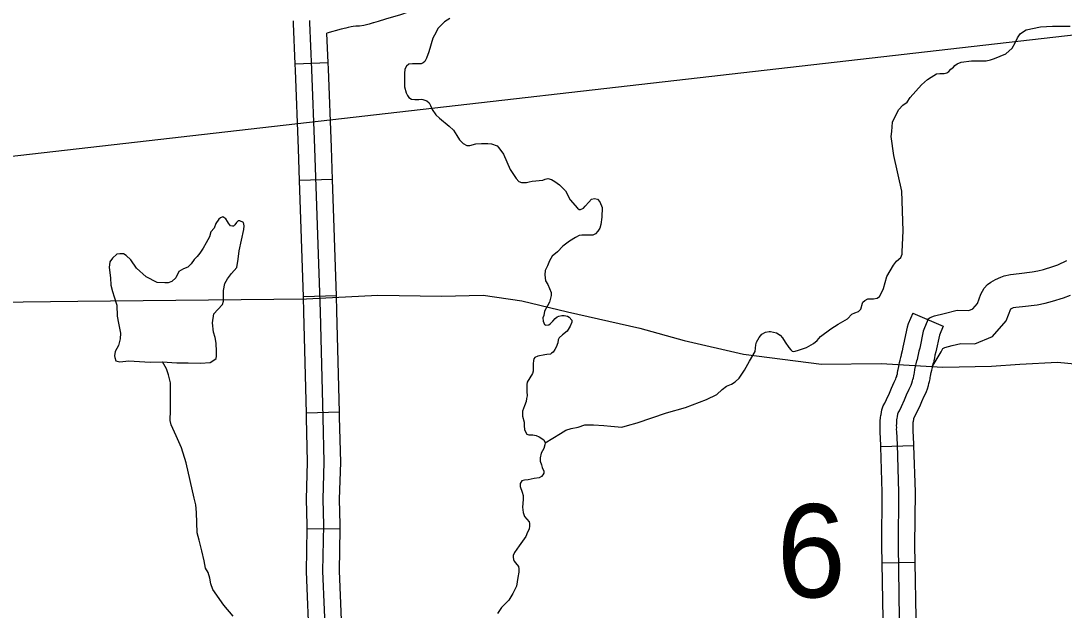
# Model space of a CAD drawing. Extents: x 1720274 to 1751788, y 372074 to 391887.
# Drawn here: x 1730713 to 1731462, y 376592 to 377014 of the extents above; entities that cross this region are included whole.
import ezdxf

# ---------------------------------------------------------------- set-up
doc = ezdxf.new("R2010")
doc.units = 0
for name, color, linetype in [('Level 32', 7, 'Continuous'), ('Level 35', 7, 'Continuous'), ('Level 43', 7, 'Continuous'), ('Level 46', 7, 'Continuous'), ('Level 5', 7, 'Continuous'), ('R_Draft', 7, 'Continuous')]:
    doc.layers.add(name, color=color, linetype=linetype)

msp = doc.modelspace()

# ---------------------------------------------------------------- linework, layer by layer
at = {"layer": 'Level 32'}
for p, q in [((1730933.83, 376984.27), (1730910.15, 376983.28)), ((1730936.9, 376900.8), (1730913.21, 376900.01)), ((1730939.71, 376817.43), (1730916.02, 376816.63)), ((1731352.96, 376804.81), (1731374.78, 376795.56)), ((1730941.88, 376733.93), (1730918.18, 376733.34)), ((1731353.87, 376709.77), (1731330.18, 376709.05)), ((1730942.4, 376650.07), (1730918.71, 376650.41)), ((1731354.76, 376626.18), (1731331.07, 376625.82))]:
    msp.add_line(p, q, dxfattribs=at)
for points in [[(1731042.66, 377038.36), (1731042.39, 377038.35), (1731040.21, 377037.88), (1731036.36, 377036.96), (1731032.32, 377036.02), (1731027.97, 377034.93), (1731022.21, 377033.15), (1731018.32, 377031.73), (1731016.08, 377030.9), (1731013.33, 377029.8), (1731008.24, 377027.48), (1730995.23, 377022.12), (1730985.7, 377018.8), (1730974.95, 377015.65), (1730969.76, 377014), (1730966.42, 377013.01)], [(1730910.15, 376983.28), (1730908.93, 377012.6), (1730908.88, 377014.4)], [(1730932.45, 376564.63), (1730930.11, 376619.99), (1730930.6, 376653.04), (1730930.12, 376671.6), (1730930.97, 376698.04), (1730930.12, 376730.24), (1730928.24, 376805.99), (1730924.28, 376923.2), (1730922.17, 376979.44), (1730920.77, 377013), (1730920.73, 377014.7)], [(1730966.42, 377013.01), (1730966.04, 377012.9), (1730964.77, 377012.57), (1730963.13, 377012.02), (1730959.48, 377011.15), (1730956.31, 377010.67), (1730953.62, 377010.53), (1730951.73, 377010.31), (1730950.32, 377010.02), (1730948.17, 377009.62), (1730946.46, 377009.2), (1730943.14, 377008.34), (1730932.94, 377005.66)], [(1730933.83, 376984.27), (1730932.94, 377005.66)], [(1730913.21, 376900.01), (1730912.44, 376922.78), (1730910.33, 376978.97), (1730910.15, 376983.28)], [(1730936.9, 376900.8), (1730936.13, 376923.63), (1730934.01, 376979.91), (1730933.83, 376984.27)], [(1730916.02, 376816.63), (1730913.21, 376900.01)], [(1730939.71, 376817.43), (1730936.9, 376900.8)], [(1730918.18, 376733.34), (1730916.39, 376805.64), (1730916.02, 376816.63)], [(1730941.88, 376733.93), (1730940.08, 376806.33), (1730939.71, 376817.43)], [(1731352.96, 376804.81), (1731349.72, 376797.18), (1731349.06, 376794.92), (1731346.46, 376782.6), (1731345.92, 376780.49), (1731345.33, 376777.96), (1731344.79, 376775.42), (1731344.45, 376773.57)], [(1731363.87, 376800.19), (1731360.9, 376793.18), (1731360.56, 376792.03), (1731358, 376779.89), (1731357.42, 376777.65), (1731356.9, 376775.39), (1731356.42, 376773.13), (1731356.1, 376771.41)], [(1731374.78, 376795.56), (1731372.07, 376789.18), (1731372.06, 376789.13), (1731369.54, 376777.19), (1731368.93, 376774.81), (1731368.47, 376772.83), (1731368.05, 376770.83), (1731367.76, 376769.26)], [(1731330.18, 376709.05), (1731330.14, 376710.25), (1731329.65, 376719.73), (1731329.6, 376721.52), (1731329.62, 376722.75), (1731329.54, 376724.39), (1731329.61, 376725.88), (1731329.61, 376727.56), (1731329.88, 376730.05), (1731330.15, 376731.58), (1731330.28, 376732.41), (1731330.8, 376735.7), (1731331.72, 376738.45), (1731332.88, 376740.48), (1731334.13, 376743.08), (1731336.3, 376747.7), (1731337.78, 376751.22), (1731339.77, 376755.46), (1731340.4, 376756.82), (1731340.8, 376757.75), (1731341.2, 376758.77), (1731341.48, 376759.6), (1731341.62, 376760.23), (1731341.94, 376761.39), (1731342.12, 376762.28), (1731342.4, 376763.77), (1731342.57, 376764.48), (1731342.91, 376766.66), (1731343.51, 376769.47), (1731343.97, 376771.3), (1731344.38, 376773.19), (1731344.45, 376773.57)], [(1731343.51, 376586.21), (1731342.73, 376638.38), (1731343.01, 376676.74), (1731341.98, 376710.74), (1731341.49, 376720.21), (1731341.45, 376721.57), (1731341.48, 376722.94), (1731341.4, 376724.4), (1731341.46, 376725.59), (1731341.46, 376726.93), (1731341.62, 376728.38), (1731341.83, 376729.59), (1731341.98, 376730.54), (1731342.35, 376732.89), (1731342.58, 376733.59), (1731343.37, 376734.96), (1731344.83, 376737.99), (1731347.13, 376742.88), (1731348.61, 376746.41), (1731350.51, 376750.45), (1731351.23, 376752), (1731351.77, 376753.26), (1731352.33, 376754.7), (1731352.89, 376756.35), (1731353.12, 376757.35), (1731353.48, 376758.67), (1731353.75, 376760.03), (1731353.98, 376761.26), (1731354.2, 376762.15), (1731354.57, 376764.51), (1731355.06, 376766.79), (1731355.51, 376768.6), (1731356, 376770.85), (1731356.1, 376771.41)], [(1731353.87, 376709.77), (1731353.82, 376711.23), (1731353.33, 376720.69), (1731353.3, 376721.63), (1731353.33, 376723.13), (1731353.27, 376724.42), (1731353.31, 376725.3), (1731353.31, 376726.3), (1731353.35, 376726.72), (1731353.51, 376727.6), (1731353.68, 376728.67), (1731353.78, 376729.3), (1731353.86, 376729.44), (1731355.53, 376732.9), (1731357.96, 376738.06), (1731359.45, 376741.59), (1731361.25, 376745.44), (1731362.05, 376747.18), (1731362.74, 376748.78), (1731363.46, 376750.63), (1731364.31, 376753.1), (1731364.62, 376754.48), (1731365.02, 376755.96), (1731365.38, 376757.77), (1731365.57, 376758.74), (1731365.83, 376759.82), (1731366.23, 376762.36), (1731366.6, 376764.11), (1731367.05, 376765.9), (1731367.62, 376768.51), (1731367.76, 376769.26)], [(1730918.71, 376650.42), (1730918.74, 376652.98), (1730918.26, 376671.63), (1730919.11, 376698.07), (1730918.27, 376729.94), (1730918.18, 376733.34)], [(1730942.4, 376650.07), (1730942.45, 376653.11), (1730941.97, 376671.56), (1730942.82, 376698.01), (1730941.96, 376730.54), (1730941.88, 376733.93)], [(1731331.07, 376625.82), (1731330.88, 376638.33), (1731331.16, 376676.61), (1731330.18, 376709.05)], [(1731354.76, 376626.18), (1731354.58, 376638.42), (1731354.86, 376676.88), (1731353.87, 376709.77)], [(1730920.51, 376566.37), (1730918.26, 376619.82), (1730918.71, 376650.41)], [(1730944.19, 376567.37), (1730941.97, 376620.15), (1730942.4, 376650.07)], [(1731333.51, 376542.16), (1731332.87, 376558.69), (1731331.67, 376585.86), (1731331.07, 376625.82)], [(1731357.19, 376543.08), (1731356.55, 376559.67), (1731355.36, 376586.56), (1731354.76, 376626.18)]]:
    msp.add_lwpolyline(points, dxfattribs=at)
at = {"layer": 'Level 35'}
for points in [[(1731021.01, 377016.14), (1731017.31, 377013.67), (1731014.84, 377011.43), (1731012.38, 377008.85), (1731011.15, 377006.27), (1731008.79, 377002.11), (1731005.99, 376992.13), (1731004.42, 376987.76), (1731003.19, 376985.4), (1731001.96, 376984.28), (1731000.39, 376983.72), (1730998.82, 376983.72), (1730997.25, 376983.72), (1730994.22, 376983.61), (1730991.76, 376983.27), (1730990.08, 376981.92), (1730988.85, 376979.79), (1730988.62, 376976.76), (1730988.62, 376967.23), (1730989.85, 376962.85), (1730990.64, 376960.95), (1730991.76, 376959.38), (1730993.66, 376958.25), (1730995.91, 376958.03), (1730997.25, 376958.14), (1730998.93, 376958.14), (1731000.5, 376958.25), (1731001.62, 376958.14), (1731004.65, 376957.02), (1731006.33, 376955.56), (1731007.11, 376953.77), (1731008.34, 376950.96), (1731010.92, 376947.15), (1731013.72, 376944.57), (1731020.67, 376938.85), (1731023.58, 376936.04), (1731026.05, 376932.23), (1731028.07, 376929.09), (1731030.64, 376926.4), (1731033.33, 376925.05), (1731035.46, 376925.16), (1731039.72, 376926.28), (1731043.76, 376926.62), (1731048.35, 376926.4), (1731051.04, 376926.17), (1731054.96, 376924.82), (1731056.31, 376923.37), (1731059.56, 376918.77), (1731064.38, 376907.77), (1731068.63, 376901.38), (1731070.54, 376899.36), (1731072.33, 376898.58), (1731076.14, 376898.58), (1731077.94, 376899.02), (1731080.06, 376899.59), (1731087.68, 376900.15), (1731089.48, 376900.93), (1731091.38, 376901.38), (1731093.85, 376900.82), (1731096.31, 376899.25), (1731099.79, 376896.89), (1731104.05, 376892.63), (1731107.41, 376886.24), (1731112.56, 376880.07), (1731113.91, 376879.28), (1731114.69, 376879.28), (1731116.93, 376880.18), (1731118.17, 376881.64), (1731120.63, 376884.44), (1731122.54, 376886.57), (1731124.89, 376887.13), (1731126.91, 376886.69), (1731128.7, 376884.78), (1731130.27, 376880.74), (1731130.16, 376873.67), (1731129.26, 376868.4), (1731128.7, 376865.93), (1731127.24, 376863.69), (1731125.45, 376861.78), (1731123.55, 376860.77)], [(1731429.93, 377005.05), (1731431.66, 377006.39), (1731434.35, 377007.93), (1731444.52, 377010.04), (1731453.16, 377010.62), (1731465.83, 377010.62)], [(1731089.48, 376711.92), (1731100.3, 376718.73), (1731104.34, 376721.03), (1731108.17, 376722.38), (1731112.97, 376723.15), (1731117.97, 376724.88), (1731124.11, 376724.88), (1731131.4, 376724.49), (1731136.59, 376723.91), (1731144.46, 376723.15), (1731148.49, 376724.49), (1731155.4, 376726.22), (1731176.33, 376733.52), (1731189.96, 376737.37), (1731205.12, 376743.13), (1731212.42, 376746.59), (1731216.26, 376750.24), (1731219.52, 376752.55), (1731222.98, 376754.08), (1731225.67, 376755.62), (1731228.55, 376758.31), (1731232.39, 376764.08), (1731235.84, 376770.42), (1731240.06, 376777.53), (1731240.45, 376782.14), (1731240.83, 376784.25), (1731242.75, 376787.52), (1731244.86, 376789.83), (1731247.36, 376791.36), (1731250.05, 376791.75), (1731251.01, 376791.75), (1731255.23, 376790.79), (1731257.92, 376789.25), (1731259.65, 376787.14), (1731261.57, 376784.25), (1731264.25, 376780.22), (1731265.6, 376778.68), (1731266.56, 376777.72), (1731267.71, 376777.53), (1731270.4, 376778.1), (1731276.73, 376780.41), (1731281.92, 376783.1), (1731284.41, 376785.41), (1731286.91, 376788.29), (1731294.2, 376793.67), (1731299.39, 376796.94), (1731306.11, 376800.78), (1731309.37, 376804.24), (1731311.48, 376805.2), (1731314.17, 376806.16), (1731315.7, 376807.7), (1731317.05, 376812.12), (1731317.24, 376812.89), (1731318.58, 376814.04), (1731320.7, 376815.19), (1731324.73, 376815.19), (1731327.41, 376815.77), (1731329.14, 376816.92), (1731330.1, 376818.65), (1731332.02, 376822.69), (1731334.33, 376831.14), (1731339.13, 376839.4), (1731341.24, 376842.29), (1731344.5, 376844.78), (1731345.46, 376847.09), (1731345.46, 376848.82), (1731346.04, 376863.81), (1731345.08, 376892.25), (1731339.51, 376917.81), (1731337.4, 376931.45), (1731337.97, 376935.1), (1731338.36, 376941.83), (1731340.66, 376946.25), (1731342.97, 376950.86), (1731345.84, 376953.93), (1731348.92, 376956.24), (1731351.22, 376959.5), (1731359.28, 376968.54), (1731363.51, 376972.38), (1731366.19, 376974.11), (1731370.03, 376976.42), (1731372.34, 376976.61), (1731374.07, 376976.8), (1731375.41, 376976.8), (1731377.52, 376977.18), (1731378.87, 376978.14), (1731380.21, 376979.68), (1731382.13, 376981.22), (1731383.28, 376982.37), (1731384.82, 376983.72), (1731387.7, 376984.87), (1731395.18, 376985.83), (1731399.98, 376985.83), (1731405.74, 376985.83), (1731408.62, 376986.41), (1731411.69, 376987.37), (1731419.76, 376990.83), (1731424.17, 376994.86), (1731426.48, 376998.71), (1731428.01, 377002.36), (1731429.93, 377005.05)], [(1731123.55, 376860.77), (1731120.52, 376860.77), (1731118.39, 376860.77), (1731115.81, 376860.88), (1731113.91, 376860.66), (1731111.11, 376859.2), (1731106.85, 376856.51), (1731102.14, 376852.92), (1731098.33, 376848.88), (1731094.52, 376845.85), (1731092.5, 376842.49), (1731091.05, 376838.79), (1731089.48, 376835.42), (1731089.14, 376832.39), (1731089.7, 376828.13), (1731091.38, 376825.55), (1731093.74, 376819.83), (1731093.74, 376817.7), (1731092.5, 376812.76), (1731091.05, 376810.29), (1731088.92, 376806.37), (1731088.36, 376803.23), (1731087.8, 376801.54), (1731088.02, 376799.3), (1731088.92, 376796.83), (1731089.93, 376796.27), (1731092.06, 376796.61), (1731092.95, 376797.39), (1731094.97, 376799.3), (1731096.65, 376801.1), (1731097.99, 376802.22), (1731099.23, 376802.89), (1731101.47, 376803.34), (1731102.93, 376803.34), (1731105.39, 376802.89), (1731106.62, 376802.1), (1731108.53, 376799.97), (1731108.64, 376798.4), (1731107.3, 376795.6), (1731105.17, 376792.12), (1731101.81, 376789.43), (1731099.56, 376787.3), (1731098.78, 376785.84), (1731098.44, 376783.71), (1731097.21, 376780.57), (1731096.31, 376779), (1731095.08, 376776.87), (1731093.96, 376776.19), (1731093.18, 376775.52), (1731090.71, 376775.29), (1731089.14, 376775.18), (1731084.1, 376774.17), (1731082.08, 376773.05), (1731081.3, 376772.15), (1731080.96, 376770.92), (1731080.85, 376768.56), (1731080.74, 376765.65), (1731080.74, 376763.4), (1731080.29, 376761.72), (1731076.48, 376755.55), (1731076.25, 376753.76), (1731076.25, 376751.18), (1731076.25, 376748.82), (1731076.48, 376745.79), (1731076.14, 376743.66), (1731075.81, 376741.53), (1731074.57, 376738.5), (1731073.9, 376736.71), (1731073.12, 376734.8), (1731073.12, 376733), (1731073.23, 376731.1), (1731074.35, 376726.83), (1731074.35, 376724.14), (1731074.69, 376721.56), (1731075.25, 376719.77), (1731076.25, 376718.31), (1731077.6, 376717.64), (1731079.17, 376717.64), (1731080.51, 376717.64), (1731082.98, 376717.3), (1731085, 376716.18), (1731088.47, 376714.16), (1731089.48, 376711.92), (1731089.14, 376710.46), (1731088.47, 376707.99), (1731086.56, 376704.51), (1731085.89, 376701.26), (1731085.78, 376698.9), (1731086.79, 376696.21), (1731087.24, 376694.42), (1731088.36, 376691.61), (1731088.36, 376690.27), (1731087.8, 376689.03), (1731086.68, 376687.8), (1731085.11, 376686.9), (1731081.63, 376686.34), (1731077.15, 376685.44), (1731074.69, 376685.33), (1731072.78, 376684.66), (1731071.55, 376682.86), (1731071.44, 376680.62)], [(1730865.82, 376587.69), (1730859.03, 376595.54), (1730851.19, 376606.78), (1730849.7, 376611.03), (1730849.07, 376615.06), (1730847.8, 376619.09), (1730845.89, 376622.27), (1730844.83, 376627.36), (1730843.34, 376634.58), (1730841.22, 376642.22), (1730839.95, 376647.52), (1730839.53, 376662.16), (1730838.89, 376667.47), (1730837.62, 376672.35), (1730832.11, 376697.6), (1730828.72, 376708.42), (1730824.9, 376717.12), (1730821.3, 376724.97), (1730820.45, 376727.94), (1730820.66, 376735.37), (1730820.66, 376738.76), (1730820.87, 376747.46), (1730820.66, 376754.89), (1730819.39, 376760.62), (1730817.91, 376765.07), (1730815.15, 376770.16)], [(1731071.44, 376680.62), (1731073, 376676.69), (1731073.57, 376674.22), (1731073.68, 376671.42), (1731073.23, 376665.81), (1731073.57, 376662), (1731074.57, 376659.3), (1731076.37, 376657.29), (1731078.05, 376655.49), (1731078.27, 376654.14), (1731078.27, 376652.57), (1731078.05, 376650.11), (1731076.82, 376647.86), (1731075.47, 376644.83), (1731070.88, 376638.1), (1731067.51, 376633.39), (1731066.51, 376631.15), (1731066.39, 376630.03), (1731066.62, 376628.46), (1731067.07, 376627.22), (1731068.07, 376625.88), (1731070.32, 376623.41), (1731070.65, 376621.73), (1731070.65, 376619.37), (1731069.87, 376615.56), (1731068.75, 376609.39), (1731066.17, 376604), (1731063.26, 376599.18), (1731058.1, 376594.02), (1731055.19, 376589.76)]]:
    msp.add_lwpolyline(points, dxfattribs=at)
msp.add_lwpolyline([(1730790.92, 376770.69), (1730806.25, 376769.86), (1730814.9, 376770.1), (1730825.42, 376769.39), (1730833.36, 376769.39), (1730842.25, 376769.16), (1730849.26, 376769.63), (1730851.95, 376771.19), (1730853.61, 376772.52), (1730853.78, 376774.03), (1730853.78, 376777.53), (1730853.61, 376783.54), (1730852.78, 376787.37), (1730851.61, 376791.38), (1730850.95, 376798.05), (1730851.95, 376804.56), (1730854.61, 376807.57), (1730858.11, 376811.24), (1730858.78, 376813.57), (1730858.78, 376817.08), (1730858.78, 376821.25), (1730859.78, 376826.09), (1730861.62, 376829.43), (1730864.62, 376833.43), (1730868.45, 376837.6), (1730869.28, 376843.61), (1730869.95, 376849.62), (1730873.34, 376864.88), (1730873.57, 376867.45), (1730873.1, 376869.79), (1730870.53, 376871.2), (1730869.36, 376871.2), (1730868.2, 376869.79), (1730866.79, 376868.15), (1730865.86, 376867.22), (1730865.16, 376867.22), (1730863.75, 376867.45), (1730862.35, 376869.32), (1730861.65, 376870.73), (1730860.48, 376872.6), (1730858.38, 376874), (1730856.51, 376873.3), (1730855.34, 376872.37), (1730853.23, 376869.09), (1730852.07, 376865.81), (1730849.78, 376863.3), (1730848.78, 376859.63), (1730846.28, 376855.29), (1730844.11, 376851.45), (1730841.78, 376847.95), (1730839.77, 376845.61), (1730837.77, 376843.28), (1730835.47, 376840.3), (1730833.13, 376837.96), (1730830.09, 376836.79), (1730826.82, 376834.69), (1730824.71, 376830.24), (1730821.67, 376827.67), (1730819.1, 376826.73), (1730816.77, 376826.73), (1730811.32, 376826.89), (1730803.37, 376830.87), (1730796.43, 376837.1), (1730792.22, 376843.11), (1730788.95, 376846.16), (1730787.08, 376847.33), (1730784.51, 376847.33), (1730782.17, 376847.09), (1730779.13, 376844.28), (1730777.26, 376841.71), (1730776.79, 376837.73), (1730777.73, 376830.24), (1730778.09, 376825.09), (1730779.13, 376820.41), (1730780.3, 376816.67), (1730782.17, 376810.58), (1730782.63, 376802.86), (1730783.57, 376797.71), (1730784.97, 376790.69), (1730784.74, 376786.48), (1730783.57, 376781.8), (1730781, 376777.35), (1730780.53, 376774.31), (1730780.93, 376773.17), (1730781.63, 376770.83), (1730784.42, 376770.02)], close=True, dxfattribs=at)
at = {"layer": 'Level 43'}
for points in [[(1729200.59, 376813.61), (1730164.47, 376806.25), (1730754.28, 376813.59), (1730918.4, 376815.11), (1730969.53, 376817.84), (1731015.15, 376817.22), (1731044.95, 376817.85), (1731072.79, 376813.84), (1731105.34, 376805.76), (1731157.29, 376794.1), (1731189.16, 376785.3), (1731231.58, 376775.44), (1731287.59, 376768.49), (1731330.37, 376768.83), (1731374.44, 376766.13)], [(1731374.44, 376766.13), (1731409.45, 376766.92), (1731429.68, 376768.49), (1731456.78, 376769.71), (1731479, 376767.59)]]:
    msp.add_lwpolyline(points, dxfattribs=at)
at = {"layer": 'Level 46'}
for points in [[(1731363.25, 376800.45), (1731365.55, 376801.75), (1731368.48, 376802.97), (1731375.55, 376804.66), (1731384.8, 376807), (1731393.09, 376806.81), (1731395.98, 376808.01), (1731399.3, 376811.88), (1731401.87, 376818.45), (1731404.3, 376822.77), (1731406.61, 376825.4), (1731408.88, 376827.18), (1731412.34, 376829.05), (1731416.09, 376830.82), (1731418.65, 376831.74), (1731423.13, 376832.73), (1731429.25, 376833.32), (1731438.72, 376834.43), (1731442.76, 376835.17), (1731446.75, 376836.22), (1731453.52, 376838.34), (1731457.07, 376839.64), (1731463.54, 376842.64)], [(1731366.98, 376766.49), (1731372.01, 376774.73), (1731373.27, 376777.19), (1731374.56, 376779.61), (1731375.9, 376780.37), (1731381.23, 376781.65), (1731387.49, 376783.24), (1731397.55, 376783.01), (1731410.28, 376788.29), (1731419.91, 376799.5), (1731423.22, 376807.98), (1731425.19, 376808.9), (1731425.25, 376808.93), (1731426.83, 376809.27), (1731431.77, 376809.75), (1731442.26, 376810.98), (1731447.92, 376812.02), (1731453.3, 376813.44), (1731461.14, 376815.89), (1731466.14, 376817.72)]]:
    msp.add_lwpolyline(points, dxfattribs=at)
at = {"layer": 'R_Draft'}
msp.add_line((1737452.73, 377689.1), (1728670.65, 376684.18), dxfattribs=at)

# ---------------------------------------------------------------- texts
at = {"layer": 'Level 5'}
msp.add_text('6', height=66.74, dxfattribs=at).set_placement((1731255.38, 376601.28))

doc.saveas('drawing.dxf')
